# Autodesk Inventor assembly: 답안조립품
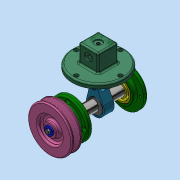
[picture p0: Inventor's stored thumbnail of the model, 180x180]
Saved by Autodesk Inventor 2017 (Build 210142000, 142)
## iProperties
Part Number: 답안조립품
Material: 일반
Document SubType Name: Assembly
Designer: MRC
Author: MRC
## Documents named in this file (17)
- C:\Users\MRC\Desktop\730206V1002\답안조립품.iam
- C:\Users\MRC\Desktop\730206V1002\본체.ipt
- C:\Users\MRC\Desktop\730206V1002\덮개.ipt
- C:\Users\MRC\Desktop\730206V1002\앞커버.ipt
- C:\Users\MRC\Desktop\730206V1002\뒤커버.ipt
- C:\Users\MRC\Desktop\730206V1002\편심축.ipt
- C:\Users\MRC\Desktop\730206V1002\베어링 17 x 40 x 12.ipt
- C:\Users\MRC\Desktop\730206V1002\링크.ipt
- C:\Users\MRC\Desktop\730206V1002\슬라이더.ipt
- C:\Users\MRC\Desktop\730206V1002\클레비스 핀 6 x 22.ipt
- 클레비스 핀 6 x 22.ipt
- C:\Users\MRC\Desktop\730206V1002\E-링.ipt
- C:\Users\MRC\Desktop\730206V1002\오일 실 17 30 8.ipt
- C:\Users\MRC\Desktop\730206V1002\키 4 x 4 x 12.ipt
- C:\Users\MRC\Desktop\730206V1002\V-벨트풀리.ipt
- C:\Users\MRC\Desktop\730206V1002\와셔 4x16.ipt
- C:\Users\MRC\Desktop\730206V1002\볼트 M4 x 10.ipt
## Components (2 placed, 2 different names)
1. E-링:1
2. V-벨트풀리:1
